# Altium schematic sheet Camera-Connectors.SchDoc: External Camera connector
size A4; Date: 25-FEB-2015; Author: A.B; CompanyName: STMicroelectronics; Address1: 12, Rue Jules HOROWITZ; Address2: 38019 Grenoble; Address3: FRANCE; DocumentNumber: MB1191; Revision: B-02; SheetNumber: 12; SheetTotal: 13; Project: STM32F746G-DISCO
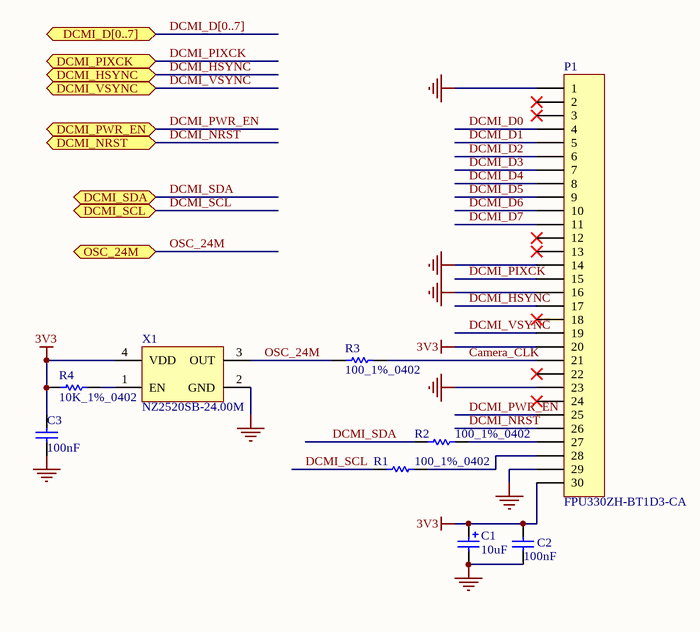
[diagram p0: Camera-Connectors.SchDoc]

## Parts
C1  10uF  [TAN-A]
C2  100nF  [0402C]
C3  100nF  [0402C]
P1  FPU330ZH-BT1D3-CA  [FPU330ZH-BT1D3-CA]
R1  100_1%_0402  [0402R]
R2  100_1%_0402  [0402R]
R3  100_1%_0402  [0402R]
R4  10K_1%_0402  [0402R]
X1  NZ2520SB-24.00M  [OSC_4SM_2R5X2R0]

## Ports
DCMI_D[0..7], DCMI_HSYNC, DCMI_NRST, DCMI_PIXCK, DCMI_PWR_EN, DCMI_SCL, DCMI_SDA, DCMI_VSYNC, OSC_24M

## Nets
3V3: C1.1 C2.2 C3.2 P1.20 P1.30 R4.1 X1.4(VDD)
GND: C1.2 C2.1 C3.1 P1.1 P1.14 P1.16 P1.23 P1.29 X1.2(GND)
Camera_CLK: P1.21 R3.2
DCMI_D0: P1.4
DCMI_D1: P1.5
DCMI_D2: P1.6
DCMI_D3: P1.7
DCMI_D4: P1.8
DCMI_D5: P1.9
DCMI_D6: P1.10
DCMI_D7: P1.11
DCMI_HSYNC: P1.17 ; port DCMI_HSYNC
DCMI_NRST: P1.26 ; port DCMI_NRST
DCMI_PIXCK: P1.15 ; port DCMI_PIXCK
DCMI_PWR_EN: P1.25 ; port DCMI_PWR_EN
DCMI_SCL: R1.1 ; port DCMI_SCL
DCMI_SDA: R2.1 ; port DCMI_SDA
DCMI_VSYNC: P1.19 ; port DCMI_VSYNC
OSC_24M: R3.1 X1.3(OUT) ; port OSC_24M
NetP1_27: P1.27 R2.2
NetP1_28: P1.28 R1.2
NetR4_2: R4.2 X1.1(EN)

Not connected (* = marked no-connect by the designer): P1 2* 3* 12* 13* 18* 22* 24*

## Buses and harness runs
bus DCMI_D[0..7] = port DCMI_D[0..7]

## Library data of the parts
C1 = Cap_10uF_POL_10%_TANA: Polarized Capacitor,10uF,10V,10%,typeA,VISHAY; Manuf_Part_1: 293D106X9010A2TE3
C2 C3 = Cap_100nF_X7R_10%_0402: Capacitor,100nF,16V,X7R,10%,0402,YAGEO; Manuf_Part_1: CC0402KRX7R7BB104
P1 = FPU330ZH-BT1D3-CA: TOWNES -  Connector FFC/FPC ZIF 0.5mm 30 pins, Lower Contacts; Manuf_Part_2: TFP-A330ZH-BT1-ECX; Description: TOWNES -  Connector FFC/FPC ZIF 0.5mm 30 pins, Lower Contacts, 52892-3033
R1-R3 = Res_100_1%_0402: Resistor,100,0402,1%,YAGEO; Manuf_Part_1: RC0402FR-07100RL; Value: 100; Order: 9239111
R4 = Res_10K_1%_0402: Resistor,10K,0402,1%,YAGEO; Manuf_Part_1: RC0402FR-0710KL
X1 = OSC_24M_NZ2520SB: Oscillator 24.00Mhz, -+50PPM, 3.3V, Temp -55 to +125°C; Manuf_Part_1: NZ2520SB 24MHz END4869A; Manuf_1: NDK; Manuf_Part_2: KC2520B24.0000C10E00; Manuf_2: AVX Corp/Kyocera Corp; ECCN_US/EU: EAR99/NEC; Ref St: 9157032; Provided: ST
